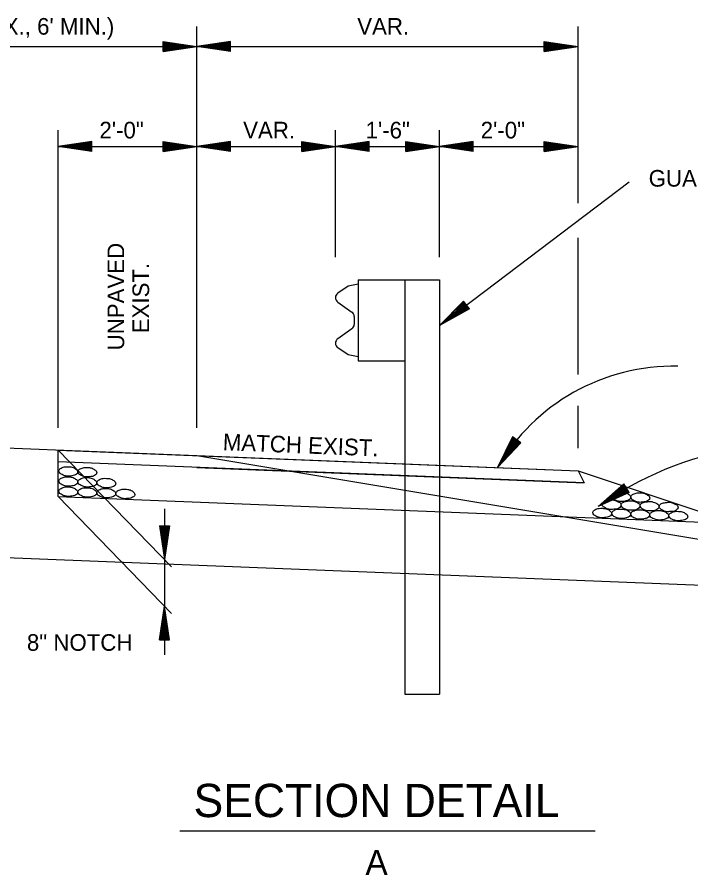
# Model space of a CAD drawing. Extents: x 1374136 to 1374281, y 380549 to 380948.
# Drawn here: x 1374150.55 to 1374174.84, y 380908.95 to 380939.9 of the extents above; entities that cross this region are included whole.
import ezdxf

# ---------------------------------------------------------------- set-up
doc = ezdxf.new("R2010")
doc.units = 0
doc.layers.add('Default', color=7, linetype='Continuous')
doc.layers.add('R_Draft', color=7, linetype='Continuous')

msp = doc.modelspace()

# ---------------------------------------------------------------- linework, layer by layer
at = {"layer": 'Default'}
for p, q in [((1374157.027, 380925.083), (1374157.027, 380939.572)), ((1374170.777, 380933.189), (1374170.777, 380939.572)), ((1374155.81, 380939.03), (1374157.027, 380938.847)), ((1374155.81, 380938.663), (1374155.81, 380939.03)), ((1374155.81, 380938.999), (1374156.823, 380938.847)), ((1374155.81, 380938.967), (1374156.614, 380938.847)), ((1374155.81, 380938.938), (1374156.41, 380938.847)), ((1374155.81, 380938.906), (1374156.206, 380938.848)), ((1374158.245, 380939.03), (1374157.027, 380938.847)), ((1374158.245, 380938.999), (1374157.232, 380938.847)), ((1374158.245, 380938.967), (1374157.441, 380938.847)), ((1374158.245, 380938.938), (1374157.645, 380938.847)), ((1374158.245, 380938.906), (1374157.849, 380938.848)), ((1374158.245, 380938.663), (1374158.245, 380939.03)), ((1374169.56, 380939.03), (1374170.777, 380938.847)), ((1374169.56, 380938.663), (1374169.56, 380939.03)), ((1374169.56, 380938.999), (1374170.573, 380938.847)), ((1374169.56, 380938.967), (1374170.364, 380938.847)), ((1374169.56, 380938.938), (1374170.16, 380938.847)), ((1374169.56, 380938.906), (1374169.956, 380938.848)), ((1374137.027, 380938.847), (1374157.027, 380938.847)), ((1374155.81, 380938.875), (1374156.002, 380938.848)), ((1374155.81, 380938.787), (1374156.206, 380938.848)), ((1374155.81, 380938.819), (1374156.002, 380938.848)), ((1374155.81, 380938.663), (1374157.027, 380938.847)), ((1374155.81, 380938.726), (1374156.614, 380938.847)), ((1374155.81, 380938.695), (1374156.823, 380938.847)), ((1374155.81, 380938.756), (1374156.41, 380938.847)), ((1374157.027, 380938.847), (1374170.777, 380938.847)), ((1374158.245, 380938.663), (1374157.027, 380938.847)), ((1374158.245, 380938.695), (1374157.232, 380938.847)), ((1374158.245, 380938.726), (1374157.441, 380938.847)), ((1374158.245, 380938.756), (1374157.645, 380938.847)), ((1374158.245, 380938.787), (1374157.849, 380938.848)), ((1374158.245, 380938.875), (1374158.053, 380938.848)), ((1374158.245, 380938.819), (1374158.053, 380938.848)), ((1374169.56, 380938.875), (1374169.752, 380938.848)), ((1374169.56, 380938.787), (1374169.956, 380938.848)), ((1374169.56, 380938.819), (1374169.752, 380938.848)), ((1374169.56, 380938.663), (1374170.777, 380938.847)), ((1374169.56, 380938.726), (1374170.364, 380938.847)), ((1374169.56, 380938.695), (1374170.573, 380938.847)), ((1374169.56, 380938.756), (1374170.16, 380938.847)), ((1374152.027, 380925.083), (1374152.027, 380935.828)), ((1374162.027, 380931.246), (1374162.027, 380935.828)), ((1374165.777, 380931.246), (1374165.777, 380935.828)), ((1374153.245, 380935.419), (1374152.027, 380935.236)), ((1374152.027, 380935.236), (1374157.027, 380935.236)), ((1374153.245, 380935.052), (1374152.027, 380935.236)), ((1374153.245, 380935.388), (1374152.232, 380935.236)), ((1374153.245, 380935.084), (1374152.232, 380935.236)), ((1374153.245, 380935.356), (1374152.441, 380935.236)), ((1374153.245, 380935.115), (1374152.441, 380935.236)), ((1374153.245, 380935.327), (1374152.645, 380935.236)), ((1374153.245, 380935.145), (1374152.645, 380935.236)), ((1374153.245, 380935.295), (1374152.849, 380935.237)), ((1374153.245, 380935.176), (1374152.849, 380935.237)), ((1374153.245, 380935.264), (1374153.053, 380935.237)), ((1374153.245, 380935.208), (1374153.053, 380935.237)), ((1374153.245, 380935.052), (1374153.245, 380935.419)), ((1374155.81, 380935.419), (1374157.027, 380935.236)), ((1374155.81, 380935.052), (1374155.81, 380935.419)), ((1374155.81, 380935.388), (1374156.823, 380935.236)), ((1374155.81, 380935.356), (1374156.614, 380935.236)), ((1374155.81, 380935.327), (1374156.41, 380935.236)), ((1374155.81, 380935.295), (1374156.206, 380935.237)), ((1374155.81, 380935.264), (1374156.002, 380935.237)), ((1374155.81, 380935.176), (1374156.206, 380935.237)), ((1374155.81, 380935.208), (1374156.002, 380935.237)), ((1374155.81, 380935.052), (1374157.027, 380935.236)), ((1374155.81, 380935.115), (1374156.614, 380935.236)), ((1374155.81, 380935.084), (1374156.823, 380935.236)), ((1374155.81, 380935.145), (1374156.41, 380935.236)), ((1374158.245, 380935.419), (1374157.027, 380935.236)), ((1374157.027, 380935.236), (1374162.027, 380935.236)), ((1374158.245, 380935.052), (1374157.027, 380935.236)), ((1374158.245, 380935.388), (1374157.232, 380935.236)), ((1374158.245, 380935.084), (1374157.232, 380935.236)), ((1374158.245, 380935.356), (1374157.441, 380935.236)), ((1374158.245, 380935.115), (1374157.441, 380935.236)), ((1374158.245, 380935.327), (1374157.645, 380935.236)), ((1374158.245, 380935.145), (1374157.645, 380935.236)), ((1374158.245, 380935.295), (1374157.849, 380935.237)), ((1374158.245, 380935.176), (1374157.849, 380935.237)), ((1374158.245, 380935.264), (1374158.053, 380935.237)), ((1374158.245, 380935.208), (1374158.053, 380935.237)), ((1374158.245, 380935.052), (1374158.245, 380935.419)), ((1374160.81, 380935.419), (1374162.027, 380935.236)), ((1374160.81, 380935.052), (1374160.81, 380935.419)), ((1374160.81, 380935.388), (1374161.823, 380935.236)), ((1374160.81, 380935.356), (1374161.614, 380935.236)), ((1374160.81, 380935.327), (1374161.41, 380935.236)), ((1374160.81, 380935.295), (1374161.206, 380935.237)), ((1374160.81, 380935.264), (1374161.002, 380935.237)), ((1374160.81, 380935.176), (1374161.206, 380935.237)), ((1374160.81, 380935.208), (1374161.002, 380935.237)), ((1374160.81, 380935.052), (1374162.027, 380935.236)), ((1374160.81, 380935.115), (1374161.614, 380935.236)), ((1374160.81, 380935.084), (1374161.823, 380935.236)), ((1374160.81, 380935.145), (1374161.41, 380935.236)), ((1374163.245, 380935.419), (1374162.027, 380935.236)), ((1374162.027, 380935.236), (1374165.777, 380935.236)), ((1374163.245, 380935.052), (1374162.027, 380935.236)), ((1374163.245, 380935.388), (1374162.232, 380935.236)), ((1374163.245, 380935.084), (1374162.232, 380935.236)), ((1374163.245, 380935.356), (1374162.441, 380935.236)), ((1374163.245, 380935.115), (1374162.441, 380935.236)), ((1374163.245, 380935.327), (1374162.645, 380935.236)), ((1374163.245, 380935.145), (1374162.645, 380935.236)), ((1374163.245, 380935.295), (1374162.849, 380935.237)), ((1374163.245, 380935.176), (1374162.849, 380935.237)), ((1374163.245, 380935.264), (1374163.053, 380935.237)), ((1374163.245, 380935.208), (1374163.053, 380935.237)), ((1374163.245, 380935.052), (1374163.245, 380935.419)), ((1374164.56, 380935.419), (1374165.777, 380935.236)), ((1374164.56, 380935.052), (1374164.56, 380935.419)), ((1374164.56, 380935.388), (1374165.573, 380935.236)), ((1374164.56, 380935.356), (1374165.364, 380935.236)), ((1374164.56, 380935.327), (1374165.16, 380935.236)), ((1374164.56, 380935.295), (1374164.956, 380935.237)), ((1374164.56, 380935.264), (1374164.752, 380935.237)), ((1374164.56, 380935.176), (1374164.956, 380935.237)), ((1374164.56, 380935.208), (1374164.752, 380935.237)), ((1374164.56, 380935.052), (1374165.777, 380935.236)), ((1374164.56, 380935.115), (1374165.364, 380935.236)), ((1374164.56, 380935.084), (1374165.573, 380935.236)), ((1374164.56, 380935.145), (1374165.16, 380935.236)), ((1374166.995, 380935.419), (1374165.777, 380935.236)), ((1374165.777, 380935.236), (1374170.777, 380935.236)), ((1374166.995, 380935.052), (1374165.777, 380935.236)), ((1374166.995, 380935.388), (1374165.982, 380935.236)), ((1374166.995, 380935.084), (1374165.982, 380935.236)), ((1374166.995, 380935.356), (1374166.191, 380935.236)), ((1374166.995, 380935.115), (1374166.191, 380935.236)), ((1374166.995, 380935.327), (1374166.395, 380935.236)), ((1374166.995, 380935.145), (1374166.395, 380935.236)), ((1374166.995, 380935.295), (1374166.599, 380935.237)), ((1374166.995, 380935.176), (1374166.599, 380935.237)), ((1374166.995, 380935.264), (1374166.803, 380935.237)), ((1374166.995, 380935.208), (1374166.803, 380935.237)), ((1374166.995, 380935.052), (1374166.995, 380935.419)), ((1374169.56, 380935.419), (1374170.777, 380935.236)), ((1374169.56, 380935.052), (1374169.56, 380935.419)), ((1374169.56, 380935.388), (1374170.573, 380935.236)), ((1374169.56, 380935.356), (1374170.364, 380935.236)), ((1374169.56, 380935.327), (1374170.16, 380935.236)), ((1374169.56, 380935.295), (1374169.956, 380935.237)), ((1374169.56, 380935.264), (1374169.752, 380935.237)), ((1374169.56, 380935.176), (1374169.956, 380935.237)), ((1374169.56, 380935.208), (1374169.752, 380935.237)), ((1374169.56, 380935.052), (1374170.777, 380935.236)), ((1374169.56, 380935.115), (1374170.364, 380935.236)), ((1374169.56, 380935.084), (1374170.573, 380935.236)), ((1374169.56, 380935.145), (1374170.16, 380935.236)), ((1374165.777, 380928.783), (1374172.623, 380933.957)), ((1374170.777, 380927.013), (1374170.777, 380931.935)), ((1374162.852, 380930.266), (1374162.489, 380930.195)), ((1374162.852, 380930.423), (1374165.777, 380930.423)), ((1374162.852, 380930.423), (1374162.852, 380927.498)), ((1374164.527, 380930.423), (1374164.527, 380915.475)), ((1374165.777, 380930.423), (1374165.777, 380915.475)), ((1374162.489, 380930.195), (1374162.113, 380929.943)), ((1374162.11, 380929.623), (1374162.622, 380929.264)), ((1374166.64, 380929.661), (1374165.777, 380928.783)), ((1374166.66, 380929.639), (1374165.939, 380928.904)), ((1374166.857, 380929.373), (1374166.64, 380929.661)), ((1374166.857, 380929.373), (1374165.777, 380928.783)), ((1374166.842, 380929.395), (1374165.939, 380928.904)), ((1374166.681, 380929.61), (1374166.112, 380929.036)), ((1374166.819, 380929.421), (1374166.112, 380929.036)), ((1374166.694, 380929.586), (1374166.272, 380929.156)), ((1374166.801, 380929.446), (1374166.272, 380929.156)), ((1374166.713, 380929.565), (1374166.432, 380929.279)), ((1374166.781, 380929.472), (1374166.432, 380929.279)), ((1374166.731, 380929.539), (1374166.596, 380929.403)), ((1374166.768, 380929.499), (1374166.596, 380929.403)), ((1374162.704, 380929.105), (1374162.704, 380928.961)), ((1374162.704, 380928.961), (1374162.704, 380928.817)), ((1374162.622, 380928.658), (1374162.11, 380928.299)), ((1374162.113, 380927.979), (1374162.489, 380927.727)), ((1374162.489, 380927.727), (1374162.852, 380927.656)), ((1374162.852, 380927.498), (1374164.527, 380927.498)), ((1374170.777, 380924.356), (1374170.777, 380925.879)), ((1374137.027, 380924.883), (1374157.027, 380924.083)), ((1374168.416, 380924.755), (1374167.869, 380923.65)), ((1374168.438, 380924.733), (1374167.986, 380923.818)), ((1374168.466, 380924.716), (1374168.105, 380923.991)), ((1374168.489, 380924.7), (1374168.219, 380924.154)), ((1374168.517, 380924.683), (1374168.338, 380924.325)), ((1374168.715, 380924.544), (1374168.416, 380924.755)), ((1374168.545, 380924.663), (1374168.457, 380924.49)), ((1374168.715, 380924.544), (1374167.869, 380923.65)), ((1374168.692, 380924.563), (1374167.986, 380923.818)), ((1374168.662, 380924.578), (1374168.105, 380923.991)), ((1374168.639, 380924.597), (1374168.219, 380924.154)), ((1374168.614, 380924.613), (1374168.338, 380924.325)), ((1374168.589, 380924.633), (1374168.457, 380924.49)), ((1374156.117, 380920.064), (1374152.027, 380924.283)), ((1374152.027, 380922.608), (1374152.027, 380924.283)), ((1374157.027, 380924.083), (1374170.777, 380923.533)), ((1374157.027, 380924.083), (1374194.756, 380917.795)), ((1374157.027, 380923.658), (1374170.994, 380923.1)), ((1374170.777, 380923.533), (1374181.227, 380920.05)), ((1374170.777, 380923.533), (1374170.994, 380923.1)), ((1374172.425, 380923.058), (1374171.502, 380922.243)), ((1374172.443, 380923.03), (1374171.674, 380922.352)), ((1374172.459, 380923.004), (1374171.848, 380922.467)), ((1374172.475, 380922.98), (1374172.018, 380922.578)), ((1374172.573, 380922.824), (1374172.018, 380922.578)), ((1374172.491, 380922.952), (1374172.19, 380922.689)), ((1374172.557, 380922.85), (1374172.19, 380922.689)), ((1374172.509, 380922.926), (1374172.365, 380922.8)), ((1374172.541, 380922.879), (1374172.365, 380922.8)), ((1374172.625, 380922.749), (1374172.425, 380923.058)), ((1374156.117, 380918.389), (1374152.027, 380922.608)), ((1374152.027, 380922.608), (1374176.488, 380921.63)), ((1374172.625, 380922.749), (1374171.502, 380922.243)), ((1374172.607, 380922.775), (1374171.674, 380922.352)), ((1374172.588, 380922.801), (1374171.848, 380922.467)), ((1374155.86, 380922.164), (1374155.86, 380916.888)), ((1374155.683, 380921.547), (1374155.86, 380920.33)), ((1374155.683, 380921.547), (1374156.045, 380921.546)), ((1374155.71, 380921.548), (1374155.859, 380920.531)), ((1374155.745, 380921.546), (1374155.861, 380920.748)), ((1374155.776, 380921.546), (1374155.861, 380920.949)), ((1374155.809, 380921.546), (1374155.863, 380921.151)), ((1374155.838, 380921.551), (1374155.864, 380921.356)), ((1374156.014, 380921.549), (1374155.859, 380920.531)), ((1374156.045, 380921.546), (1374155.86, 380920.33)), ((1374155.979, 380921.548), (1374155.861, 380920.748)), ((1374155.952, 380921.544), (1374155.861, 380920.949)), ((1374155.924, 380921.547), (1374155.863, 380921.151)), ((1374155.892, 380921.546), (1374155.864, 380921.356)), ((1374137.027, 380920.933), (1374188.212, 380918.886)), ((1374155.677, 380917.438), (1374155.86, 380918.655)), ((1374156.038, 380917.437), (1374155.86, 380918.655)), ((1374155.704, 380917.437), (1374155.858, 380918.453)), ((1374155.738, 380917.439), (1374155.859, 380918.236)), ((1374156.008, 380917.434), (1374155.858, 380918.453)), ((1374155.972, 380917.435), (1374155.859, 380918.236)), ((1374155.769, 380917.438), (1374155.858, 380918.035)), ((1374155.945, 380917.44), (1374155.858, 380918.035)), ((1374155.802, 380917.439), (1374155.859, 380917.833)), ((1374155.832, 380917.433), (1374155.858, 380917.628)), ((1374155.885, 380917.438), (1374155.858, 380917.628)), ((1374155.917, 380917.436), (1374155.859, 380917.833)), ((1374155.677, 380917.438), (1374156.038, 380917.437)), ((1374156.41, 380910.538), (1374171.395, 380910.538))]:
    msp.add_line(p, q, dxfattribs=at)
msp.add_lwpolyline([(1374152.027, 380923.858), (1374152.027, 380924.283), (1374170.777, 380923.533), (1374170.994, 380923.1)], close=True, dxfattribs=at)
for centre, radius, start, end in [((1374162.222, 380929.782), 0.195, 124.158, 234.7471), ((1374162.509, 380929.105), 0.195, 360, 54.7471), ((1374162.509, 380928.817), 0.195, 305.2529, 0), ((1374162.222, 380928.14), 0.195, 125.2529, 235.842), ((1374174.22, 380919.968), 7.341, 88.8267, 149.8977), ((1374178.504, 380912.471), 12.021, 73.3815, 125.6318)]:
    msp.add_arc(centre, radius, start, end, dxfattribs=at)
for points in [[(1374152.399, 380923.681), (1374152.279, 380923.68), (1374152.132, 380923.631), (1374152.062, 380923.566), (1374152.05, 380923.523), (1374152.085, 380923.449), (1374152.129, 380923.416), (1374152.205, 380923.378), (1374152.324, 380923.344), (1374152.383, 380923.339), (1374152.474, 380923.345), (1374152.573, 380923.362), (1374152.65, 380923.39), (1374152.72, 380923.447), (1374152.731, 380923.49), (1374152.71, 380923.556), (1374152.656, 380923.601), (1374152.606, 380923.638), (1374152.526, 380923.665), (1374152.475, 380923.677), (1374152.399, 380923.681)], [(1374153.085, 380923.654), (1374152.965, 380923.652), (1374152.818, 380923.603), (1374152.748, 380923.539), (1374152.736, 380923.495), (1374152.771, 380923.422), (1374152.815, 380923.388), (1374152.891, 380923.351), (1374153.01, 380923.316), (1374153.069, 380923.312), (1374153.16, 380923.317), (1374153.259, 380923.334), (1374153.336, 380923.362), (1374153.406, 380923.419), (1374153.417, 380923.463), (1374153.397, 380923.529), (1374153.343, 380923.573), (1374153.292, 380923.611), (1374153.212, 380923.637), (1374153.161, 380923.649), (1374153.085, 380923.654)], [(1374152.399, 380923.316), (1374152.279, 380923.315), (1374152.132, 380923.266), (1374152.062, 380923.201), (1374152.05, 380923.158), (1374152.085, 380923.084), (1374152.129, 380923.051), (1374152.205, 380923.013), (1374152.324, 380922.979), (1374152.383, 380922.974), (1374152.474, 380922.98), (1374152.573, 380922.997), (1374152.65, 380923.025), (1374152.72, 380923.082), (1374152.731, 380923.125), (1374152.71, 380923.191), (1374152.656, 380923.236), (1374152.606, 380923.273), (1374152.526, 380923.3), (1374152.475, 380923.312), (1374152.399, 380923.316)], [(1374153.085, 380923.289), (1374152.965, 380923.287), (1374152.818, 380923.238), (1374152.748, 380923.174), (1374152.736, 380923.13), (1374152.771, 380923.057), (1374152.815, 380923.023), (1374152.891, 380922.986), (1374153.01, 380922.951), (1374153.069, 380922.947), (1374153.16, 380922.952), (1374153.259, 380922.969), (1374153.336, 380922.997), (1374153.406, 380923.054), (1374153.417, 380923.098), (1374153.397, 380923.164), (1374153.343, 380923.208), (1374153.292, 380923.246), (1374153.212, 380923.272), (1374153.161, 380923.284), (1374153.085, 380923.289)], [(1374153.771, 380923.262), (1374153.651, 380923.26), (1374153.504, 380923.211), (1374153.434, 380923.146), (1374153.422, 380923.103), (1374153.458, 380923.029), (1374153.501, 380922.996), (1374153.577, 380922.958), (1374153.696, 380922.924), (1374153.755, 380922.919), (1374153.846, 380922.925), (1374153.945, 380922.942), (1374154.022, 380922.97), (1374154.092, 380923.027), (1374154.103, 380923.07), (1374154.083, 380923.136), (1374154.029, 380923.181), (1374153.978, 380923.218), (1374153.898, 380923.245), (1374153.847, 380923.257), (1374153.771, 380923.262)], [(1374152.399, 380922.951), (1374152.279, 380922.95), (1374152.132, 380922.901), (1374152.062, 380922.836), (1374152.05, 380922.793), (1374152.085, 380922.719), (1374152.129, 380922.686), (1374152.205, 380922.648), (1374152.324, 380922.614), (1374152.383, 380922.609), (1374152.474, 380922.615), (1374152.573, 380922.632), (1374152.65, 380922.66), (1374152.72, 380922.717), (1374152.731, 380922.76), (1374152.71, 380922.826), (1374152.656, 380922.871), (1374152.606, 380922.908), (1374152.526, 380922.935), (1374152.475, 380922.947), (1374152.399, 380922.951)], [(1374153.085, 380922.924), (1374152.965, 380922.922), (1374152.818, 380922.873), (1374152.748, 380922.809), (1374152.736, 380922.765), (1374152.771, 380922.692), (1374152.815, 380922.658), (1374152.891, 380922.621), (1374153.01, 380922.586), (1374153.069, 380922.582), (1374153.16, 380922.587), (1374153.259, 380922.604), (1374153.336, 380922.632), (1374153.406, 380922.689), (1374153.417, 380922.733), (1374153.397, 380922.799), (1374153.343, 380922.843), (1374153.292, 380922.881), (1374153.212, 380922.907), (1374153.161, 380922.919), (1374153.085, 380922.924)], [(1374153.771, 380922.897), (1374153.651, 380922.895), (1374153.504, 380922.846), (1374153.434, 380922.781), (1374153.422, 380922.738), (1374153.458, 380922.664), (1374153.501, 380922.631), (1374153.577, 380922.593), (1374153.696, 380922.559), (1374153.755, 380922.554), (1374153.846, 380922.56), (1374153.945, 380922.577), (1374154.022, 380922.605), (1374154.092, 380922.662), (1374154.103, 380922.705), (1374154.083, 380922.771), (1374154.029, 380922.816), (1374153.978, 380922.853), (1374153.898, 380922.88), (1374153.847, 380922.892), (1374153.771, 380922.897)], [(1374154.457, 380922.869), (1374154.337, 380922.867), (1374154.19, 380922.819), (1374154.12, 380922.754), (1374154.108, 380922.71), (1374154.144, 380922.637), (1374154.187, 380922.604), (1374154.263, 380922.566), (1374154.383, 380922.531), (1374154.441, 380922.527), (1374154.532, 380922.533), (1374154.631, 380922.549), (1374154.708, 380922.577), (1374154.778, 380922.634), (1374154.789, 380922.678), (1374154.769, 380922.744), (1374154.715, 380922.789), (1374154.664, 380922.826), (1374154.584, 380922.853), (1374154.534, 380922.864), (1374154.457, 380922.869)], [(1374172.342, 380922.766), (1374172.222, 380922.764), (1374172.075, 380922.716), (1374172.005, 380922.651), (1374171.994, 380922.607), (1374172.029, 380922.534), (1374172.072, 380922.5), (1374172.148, 380922.463), (1374172.268, 380922.428), (1374172.326, 380922.424), (1374172.417, 380922.43), (1374172.516, 380922.446), (1374172.593, 380922.474), (1374172.663, 380922.531), (1374172.675, 380922.575), (1374172.654, 380922.641), (1374172.6, 380922.686), (1374172.55, 380922.723), (1374172.47, 380922.75), (1374172.419, 380922.761), (1374172.342, 380922.766)], [(1374173.028, 380922.739), (1374172.908, 380922.737), (1374172.762, 380922.688), (1374172.691, 380922.624), (1374172.68, 380922.58), (1374172.715, 380922.507), (1374172.758, 380922.473), (1374172.834, 380922.435), (1374172.954, 380922.401), (1374173.012, 380922.396), (1374173.103, 380922.402), (1374173.202, 380922.419), (1374173.279, 380922.447), (1374173.349, 380922.504), (1374173.361, 380922.548), (1374173.34, 380922.614), (1374173.286, 380922.658), (1374173.236, 380922.695), (1374173.156, 380922.722), (1374173.105, 380922.734), (1374173.028, 380922.739)], [(1374171.998, 380922.482), (1374171.87, 380922.47), (1374171.728, 380922.436), (1374171.654, 380922.368), (1374171.642, 380922.328), (1374171.677, 380922.251), (1374171.721, 380922.217), (1374171.8, 380922.172), (1374171.916, 380922.141), (1374171.975, 380922.14), (1374172.066, 380922.146), (1374172.168, 380922.152), (1374172.245, 380922.187), (1374172.312, 380922.248), (1374172.323, 380922.295), (1374172.303, 380922.361), (1374172.249, 380922.406), (1374172.198, 380922.428), (1374172.118, 380922.462), (1374172.071, 380922.478), (1374171.998, 380922.482)], [(1374172.684, 380922.455), (1374172.556, 380922.442), (1374172.414, 380922.408), (1374172.34, 380922.34), (1374172.328, 380922.3), (1374172.364, 380922.223), (1374172.407, 380922.19), (1374172.486, 380922.145), (1374172.602, 380922.114), (1374172.661, 380922.113), (1374172.752, 380922.119), (1374172.854, 380922.124), (1374172.931, 380922.16), (1374172.998, 380922.221), (1374173.009, 380922.268), (1374172.989, 380922.334), (1374172.935, 380922.378), (1374172.884, 380922.401), (1374172.804, 380922.435), (1374172.757, 380922.45), (1374172.684, 380922.455)], [(1374173.37, 380922.428), (1374173.243, 380922.415), (1374173.1, 380922.381), (1374173.026, 380922.313), (1374173.014, 380922.273), (1374173.05, 380922.196), (1374173.093, 380922.162), (1374173.172, 380922.117), (1374173.288, 380922.086), (1374173.347, 380922.085), (1374173.438, 380922.091), (1374173.54, 380922.097), (1374173.617, 380922.132), (1374173.684, 380922.193), (1374173.696, 380922.24), (1374173.675, 380922.306), (1374173.621, 380922.351), (1374173.57, 380922.373), (1374173.49, 380922.408), (1374173.443, 380922.423), (1374173.37, 380922.428)], [(1374174.056, 380922.4), (1374173.929, 380922.388), (1374173.786, 380922.353), (1374173.712, 380922.285), (1374173.7, 380922.245), (1374173.736, 380922.168), (1374173.779, 380922.135), (1374173.858, 380922.09), (1374173.975, 380922.059), (1374174.033, 380922.058), (1374174.124, 380922.064), (1374174.226, 380922.069), (1374174.303, 380922.105), (1374174.37, 380922.166), (1374174.382, 380922.213), (1374174.361, 380922.279), (1374174.307, 380922.323), (1374174.256, 380922.346), (1374174.176, 380922.38), (1374174.129, 380922.395), (1374174.056, 380922.4)], [(1374171.653, 380922.181), (1374171.533, 380922.179), (1374171.387, 380922.131), (1374171.316, 380922.066), (1374171.305, 380922.023), (1374171.34, 380921.949), (1374171.383, 380921.916), (1374171.459, 380921.878), (1374171.579, 380921.843), (1374171.637, 380921.839), (1374171.728, 380921.845), (1374171.827, 380921.861), (1374171.904, 380921.889), (1374171.974, 380921.947), (1374171.986, 380921.99), (1374171.965, 380922.056), (1374171.911, 380922.101), (1374171.861, 380922.138), (1374171.781, 380922.165), (1374171.73, 380922.176), (1374171.653, 380922.181)], [(1374172.339, 380922.154), (1374172.219, 380922.152), (1374172.073, 380922.103), (1374172.002, 380922.039), (1374171.991, 380921.995), (1374172.026, 380921.922), (1374172.069, 380921.888), (1374172.145, 380921.851), (1374172.265, 380921.816), (1374172.323, 380921.811), (1374172.414, 380921.817), (1374172.513, 380921.834), (1374172.59, 380921.862), (1374172.66, 380921.919), (1374172.672, 380921.963), (1374172.651, 380922.029), (1374172.597, 380922.073), (1374172.547, 380922.11), (1374172.467, 380922.137), (1374172.416, 380922.149), (1374172.339, 380922.154)], [(1374173.026, 380922.126), (1374172.905, 380922.125), (1374172.759, 380922.076), (1374172.688, 380922.011), (1374172.677, 380921.968), (1374172.712, 380921.894), (1374172.755, 380921.861), (1374172.831, 380921.823), (1374172.951, 380921.788), (1374173.009, 380921.784), (1374173.101, 380921.79), (1374173.199, 380921.807), (1374173.276, 380921.834), (1374173.346, 380921.892), (1374173.358, 380921.935), (1374173.337, 380922.001), (1374173.283, 380922.046), (1374173.233, 380922.083), (1374173.153, 380922.11), (1374173.102, 380922.122), (1374173.026, 380922.126)], [(1374173.712, 380922.099), (1374173.591, 380922.097), (1374173.445, 380922.048), (1374173.374, 380921.984), (1374173.363, 380921.94), (1374173.398, 380921.867), (1374173.441, 380921.833), (1374173.517, 380921.796), (1374173.637, 380921.761), (1374173.695, 380921.756), (1374173.787, 380921.762), (1374173.885, 380921.779), (1374173.962, 380921.807), (1374174.032, 380921.864), (1374174.044, 380921.908), (1374174.023, 380921.974), (1374173.969, 380922.018), (1374173.919, 380922.056), (1374173.839, 380922.082), (1374173.788, 380922.094), (1374173.712, 380922.099)], [(1374174.398, 380922.071), (1374174.277, 380922.07), (1374174.131, 380922.021), (1374174.06, 380921.956), (1374174.049, 380921.913), (1374174.084, 380921.839), (1374174.127, 380921.806), (1374174.203, 380921.768), (1374174.323, 380921.734), (1374174.381, 380921.729), (1374174.473, 380921.735), (1374174.571, 380921.752), (1374174.648, 380921.78), (1374174.718, 380921.837), (1374174.73, 380921.88), (1374174.709, 380921.946), (1374174.655, 380921.991), (1374174.605, 380922.028), (1374174.525, 380922.055), (1374174.474, 380922.067), (1374174.398, 380922.071)]]:
    msp.add_spline(points, degree=3, dxfattribs=at)
at = {"layer": 'R_Draft'}
msp.add_line((1374164.527, 380915.475), (1374165.777, 380915.475), dxfattribs=at)

# ---------------------------------------------------------------- texts
at = {"layer": 'Default'}
for s, height, p in [("EXISTING SHOULDER (10' MAX., 6' MIN.)", 0.6, (1374138.675, 380939.272)), ('VAR.', 0.6, (1374162.813, 380939.272)), ('2\'-0"', 0.6, (1374153.516, 380935.528)), ('VAR.', 0.6, (1374158.698, 380935.528)), ('1\'-6"', 0.6, (1374163.114, 380935.528)), ('2\'-0"', 0.6, (1374167.266, 380935.528)), ('GUARDRAIL (TYPE A)', 0.6, (1374173.323, 380933.789)), ('8" NOTCH', 0.6, (1374150.899, 380917.039)), ('SECTION DETAIL', 1.2, (1374156.91, 380911.038)), ('A', 0.9, (1374163.108, 380908.954))]:
    msp.add_text(s, height=height, dxfattribs=at).set_placement(p)
for s, rotation, p in [('UNPAVED', 90, (1374154.407, 380927.881)), ('EXIST.', 90, (1374155.307, 380928.497)), ('MATCH EXIST.', 357.7094, (1374157.956, 380924.279))]:
    msp.add_text(s, height=0.6, rotation=rotation, dxfattribs=at).set_placement(p)

doc.saveas('drawing.dxf')
